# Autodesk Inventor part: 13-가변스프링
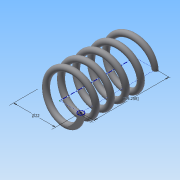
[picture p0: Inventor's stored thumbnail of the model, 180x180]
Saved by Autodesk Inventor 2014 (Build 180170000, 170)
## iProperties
Created: 2015-09
Part Number: 13-가변스프링
Material: Generic
Document SubType Name: Modeling
Designer: study
Density: 1 g/cm^3
Appearance: Default
Author: study
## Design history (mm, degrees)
sketch "스케치1"
  geometry: L1 (0, 0)-(11, 0); L2 (11, 0)-(11, 39.258); L3 (11, 39.258)-(0, 39.258); L4 (0, 39.258)-(0, 0); C1 r 1.5 at (11, 0); 1 further point
  constraints: 8 end point, 2 coincident, 2 parallel, 1 centre point, 1 horizontal, 1 perpendicular
  dimensions: "d0" = 22 diameter of L2 L4; "d1" = 39.25829 distance between parallel lines of L1 L3 (derived); "d2" = 3 diameter of C1
feature "코일1" sketch "스케치1" pitch "d3" = 10; turns "d5" = 5; dims "d4" = 39.25829 (= d1), "d6" = 0, angle "d7" = 90 deg, angle "d8" = 90 deg, "d9" = 0, "d10" = 0
node "작업 평면1"
sketch "스케치2"
  geometry: L1 (-12.5, 0)-(-9.5, 0) reference; 1 further point
  constraints: 1 horizontal alignment
extrude "돌출1" cut sketch "스케치2" stored distance "d12" = 10; taper "d13" = 0 deg
node "작업 평면2"
sketch "스케치3"
  geometry: L1 (-9.5, 0)-(-12.5, 0) reference; 1 further point
  constraints: 1 horizontal alignment
extrude "돌출2" cut sketch "스케치3" stored distance "d15" = 10; taper "d16" = 0 deg
node "솔리드1"
node "절단 모서리 투영1"
node "절단 모서리 투영2"
other parameters: "d11" = 0, "d14" = 39.25829 (= d1)
